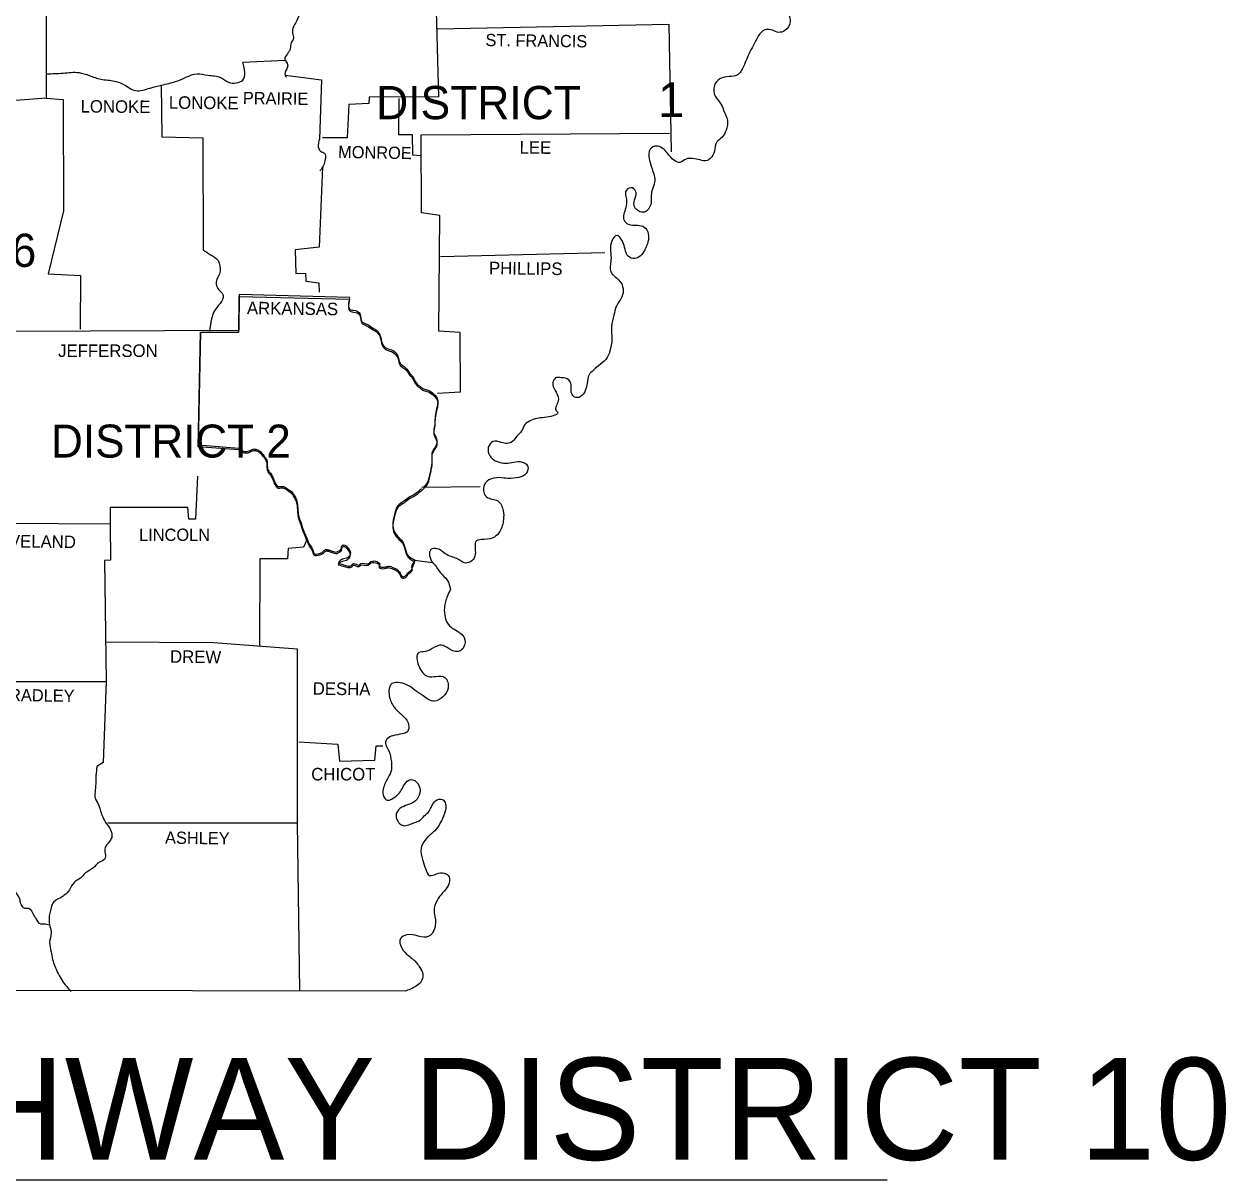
# Model space of a CAD drawing. Extents: x 171 to 3403, y 68 to 2102.
# Drawn here: x 2999.8 to 3403.5, y 1284.9 to 1673 of the extents above; entities that cross this region are included whole.
import ezdxf

# ---------------------------------------------------------------- set-up
doc = ezdxf.new("R2010")
doc.units = 0
for name, color, linetype in [('1', 7, 'Continuous'), ('2', 7, 'Continuous'), ('3', 7, 'Continuous')]:
    doc.layers.add(name, color=color, linetype=linetype)

msp = doc.modelspace()

# ---------------------------------------------------------------- linework, layer by layer
at = {"layer": '1'}
for p, q in [((3133.42, 1517.43), (3152.99, 1517.73)), ((2625.16, 1284.87), (3289.7, 1284.87))]:
    msp.add_line(p, q, dxfattribs=at)
for points in [[(3000.75, 1871.52), (3000.95, 1848.23), (2999.28, 1848.13), (2999.58, 1823.77), (2992.73, 1822.79), (2993.32, 1816.24), (2995.66, 1813.2), (2995.47, 1805.48), (2982.16, 1804.99), (2981.67, 1793.05), (2969.54, 1792.66), (2968.95, 1778.18), (2969.64, 1777), (2969.93, 1753.91), (2990.87, 1752.54), (2990.58, 1700.98), (3007.21, 1700.49), (3007.21, 1648.05), (2994.1, 1647.07), (2993.12, 1635.53), (2971.11, 1635.43)], [(3137.53, 1702.16), (3139, 1648.54), (3115.71, 1648.44), (3115.62, 1646.29), (3108.87, 1645.9), (3108.28, 1634.74), (3100.06, 1634.74)], [(3138.71, 1671.34), (3216.39, 1672.9)], [(3216.39, 1672.9), (3217.18, 1630.05)], [(3073.25, 1660.18), (3087.44, 1660.87)], [(3087.44, 1655.78), (3099.67, 1654.21), (3098.98, 1634.25)], [(3045.86, 1652.55), (3046.05, 1635.04), (3059.85, 1634.74), (3059.95, 1597.17)], [(3007.21, 1648.05), (3012.88, 1647.66), (3012.98, 1610.28), (3007.89, 1589.05), (3018.75, 1588.56), (3018.66, 1570.56)], [(3125.69, 1647.95), (3125.6, 1635.82), (3130.1, 1635.82), (3130.29, 1629.07), (3133.13, 1628.77)], [(3138.71, 1549.03), (3146.34, 1549.52), (3146.24, 1569.39), (3139.1, 1569.87), (3139.49, 1608.72), (3133.33, 1609.6), (3133.13, 1635.72), (3216.59, 1636.31)], [(3100.06, 1624.86), (3098.89, 1598.05), (3090.86, 1597.17), (3091.06, 1589.25), (3094.29, 1589.35), (3094.39, 1586.61), (3098.79, 1586.12), (3098.89, 1582.89)], [(3139.69, 1594.92), (3194.87, 1596.29)], [(3109.06, 1581.13), (3072.08, 1582.1), (3071.88, 1570.07), (2997.03, 1569.78)], [(3059.06, 1569.48), (3071.88, 1569.48), (3072.08, 1581.52), (3109.06, 1580.54)], [(3059.06, 1569.48), (3058.28, 1531.62), (3071.88, 1530.54)], [(3071.88, 1529.96), (3058.28, 1531.03), (3059.06, 1569.48)], [(3057.99, 1521.15), (3057.4, 1506.77), (3055.15, 1506.77), (3054.76, 1510.58), (3028.73, 1510.58), (3028.73, 1505.1)], [(2993.9, 1505.4), (3028.54, 1505.2)], [(3028.73, 1505.2), (3028.83, 1492.97), (3026.78, 1492.87), (3027.36, 1452.27)], [(3094.87, 1500.02), (3093.7, 1497.37), (3088.51, 1496.89), (3088.22, 1493.36), (3078.93, 1493.36), (3078.83, 1464.11)], [(3105.83, 1495.71), (3106.13, 1496.01), (3106.42, 1496.3), (3106.42, 1496.3)], [(3027.07, 1465.58), (3063.37, 1465.28), (3091.55, 1463.13)], [(3091.55, 1463.13), (3091.55, 1404.62), (3092.33, 1348.36)], [(2983.14, 1452.17), (3027.36, 1452.27)], [(3027.36, 1452.27), (3026.39, 1425.07), (3024.23, 1423.7)], [(3092.04, 1431.92), (3105.15, 1431.14), (3105.73, 1425.46), (3117.57, 1425.85), (3118.06, 1430.65), (3120.31, 1430.65)], [(2769.26, 1428.1), (2769.46, 1348.95), (3128.04, 1348.36)], [(3027.95, 1404.72), (3091.55, 1404.72)]]:
    msp.add_lwpolyline(points, dxfattribs=at)
for points in [[(3099.86, 1713.51), (3099.37, 1710.28), (3097.52, 1709.4), (3095.36, 1707.24), (3094.87, 1705.29), (3093.11, 1704.5), (3091.45, 1702.45), (3090.37, 1699.61), (3090.37, 1696.68), (3091.06, 1693.35), (3093.5, 1692.47), (3094.68, 1690.51), (3094.48, 1688.46), (3096.83, 1687.09), (3097.22, 1685.91), (3096.83, 1684.64), (3095.75, 1681.02), (3095.85, 1678.58), (3095.66, 1677.5), (3093.02, 1676.81), (3091.45, 1674.17), (3090.37, 1672.31), (3089.98, 1669.87), (3090.28, 1668.11), (3089.49, 1666.74), (3089.2, 1664.68), (3088.22, 1662.92), (3087.34, 1661.26), (3088.32, 1659.3), (3088.03, 1657.93), (3087.44, 1655.78), (3087.93, 1655.09)], [(3252.89, 1709.59), (3253.28, 1706.75), (3251.62, 1703.72), (3251.03, 1700.69), (3251.32, 1697.65), (3248.19, 1695.99), (3245.45, 1694.03), (3247.02, 1691.69), (3249.95, 1689.53), (3252.89, 1687.87), (3254.75, 1686.21), (3255.24, 1682.2), (3255.72, 1679.65), (3256.7, 1676.13), (3257.09, 1673.68), (3255.33, 1670.75), (3253.28, 1670.16), (3251.13, 1670.85), (3248.58, 1671.04), (3246.53, 1669.09), (3245.06, 1666.35), (3243.59, 1663.61), (3242.52, 1661.26), (3241.44, 1658.71), (3239.29, 1655.78), (3236.65, 1655.29), (3233.51, 1654.51), (3231.66, 1652.35), (3231.95, 1648.73), (3233.71, 1646.29), (3235.08, 1643.26), (3236.06, 1640.61), (3235.57, 1637.29), (3234.2, 1634.84), (3232.44, 1633.37), (3231.66, 1630.24), (3230.38, 1627.89), (3229.21, 1627.11), (3226.86, 1627.31), (3224.32, 1627.8), (3222.16, 1627.6), (3220.11, 1626.52), (3218.06, 1627.21), (3215.9, 1629.56), (3214.14, 1631.32), (3212.19, 1632), (3210.13, 1630.93), (3209.74, 1627.7), (3210.72, 1624.37), (3211.6, 1619.87), (3210.72, 1617.13), (3210.42, 1612.63)], [(3007.4, 1656.27), (3012.88, 1656.46), (3018.26, 1656.66), (3021.69, 1655.68), (3025.6, 1654.41), (3030.2, 1653.82), (3033.43, 1652.55), (3037.25, 1650.59), (3042.14, 1651.47), (3045.95, 1652.45), (3050.94, 1653.72), (3054.17, 1655.09), (3057.89, 1656.27), (3061.61, 1655.78), (3065.82, 1655), (3068.46, 1653.43), (3073.25, 1654.12), (3073.25, 1660.18)], [(3098.98, 1634.25), (3098.59, 1632.3), (3099.37, 1630.24), (3100.74, 1629.56), (3100.94, 1627.6), (3100.45, 1625.64), (3100.06, 1624.86), (3099.18, 1623.69)], [(3210.42, 1612.63), (3208.17, 1609.79), (3204.85, 1611.56), (3204.85, 1613.9), (3205.34, 1616.35), (3204.16, 1617.91), (3202.11, 1617.23), (3202.11, 1614.2), (3201.91, 1611.26), (3201.32, 1607.05), (3202.69, 1605.78), (3205.83, 1605.39), (3208.08, 1604.8), (3209.45, 1602.55), (3209.35, 1599.81), (3208.27, 1597.17), (3206.71, 1595.02), (3204.26, 1594.24), (3202.3, 1595.51), (3201.52, 1598.05), (3200.64, 1600.3), (3198.98, 1601.97), (3197.22, 1600.11), (3196.82, 1596.68), (3196.92, 1593.75), (3196.92, 1589.74), (3199.47, 1587.09), (3201.03, 1584.06), (3200.54, 1581.32), (3198.68, 1578.09), (3197.9, 1575.26), (3197.12, 1571.44), (3197.22, 1567.23), (3196.53, 1563.12), (3195.16, 1560.38), (3192.62, 1558.13), (3190.95, 1556.67), (3189.58, 1555.2), (3188.9, 1552.26), (3188.41, 1550.21), (3186.55, 1547.76), (3185.08, 1547.57), (3183.91, 1548.55), (3183.52, 1550.21), (3183.52, 1551.87), (3182.74, 1553.54), (3180.29, 1554.22), (3178.33, 1554.12), (3177.45, 1552.75), (3178.72, 1548.94), (3179.21, 1546.49), (3178.53, 1543.16), (3178.92, 1542.77), (3175.4, 1540.91), (3172.56, 1540.62), (3170.21, 1539.94), (3167.96, 1538.47), (3166.88, 1536.32), (3165.32, 1534.55), (3163.95, 1532.89), (3162.09, 1532.11), (3160.04, 1532.5), (3157.3, 1532.79), (3155.73, 1530.84), (3156.22, 1528), (3158.08, 1526.34), (3160.82, 1525.55), (3163.66, 1525.75), (3166.4, 1526.04), (3168.94, 1524.67), (3168.45, 1522.03), (3166, 1520.76), (3162.38, 1520.37), (3159.45, 1520.66), (3155.93, 1519.88), (3154.17, 1517.63), (3155.14, 1514.2), (3158.96, 1512.83), (3160.72, 1509.61), (3160.82, 1506.57), (3159.55, 1502.56), (3157.79, 1500.7), (3154.36, 1499.92), (3151.72, 1499.43), (3151.33, 1494.93), (3150.15, 1492.68), (3148.1, 1491.99), (3145.16, 1493.46), (3143.4, 1494.15), (3141.25, 1495.12), (3138.51, 1496.79), (3136.46, 1496.49), (3137.04, 1492.19), (3137.24, 1491.99), (3139.59, 1488.76), (3141.94, 1486.22), (3143.01, 1483.19)], [(3059.95, 1597.17), (3062.39, 1595.51), (3064.93, 1593.55), (3065.62, 1590.91), (3065.42, 1589.05), (3064.64, 1587.49), (3064.45, 1585.04), (3065.62, 1583.28), (3066.7, 1581.81), (3065.62, 1579.17), (3063.76, 1576.72), (3062.78, 1573.98), (3062.1, 1569.87)], [(3109.06, 1581.13), (3109.35, 1577.12), (3111.7, 1576.53), (3112.68, 1575.45), (3113.17, 1573.2), (3114.83, 1572.22), (3117.08, 1570.85), (3118.45, 1569.87), (3119.43, 1568.31), (3120.02, 1565.77), (3121.58, 1564.1), (3123.74, 1563.32), (3125.3, 1561.46), (3126.28, 1558.82), (3127.85, 1557.64), (3129.41, 1555.59), (3130.19, 1554.71), (3131.56, 1552.36), (3132.93, 1551.19), (3133.91, 1550.5), (3135.48, 1550.01), (3137.43, 1548.74), (3138.71, 1546.78), (3138.71, 1545.32), (3138.22, 1543.07), (3137.83, 1540.72), (3137.63, 1538.08), (3137.43, 1535.73), (3138.32, 1533.77), (3137.83, 1530.84), (3136.85, 1529.27), (3136.75, 1527.12), (3136.46, 1523.89), (3136.07, 1522.03), (3135.18, 1519), (3133.91, 1517.43)], [(3109.06, 1580.54), (3109.35, 1576.53), (3111.7, 1575.94), (3112.68, 1574.86), (3113.17, 1572.61), (3114.83, 1571.64), (3117.08, 1570.27), (3118.45, 1569.29), (3119.43, 1567.72), (3120.02, 1565.18), (3121.58, 1563.52), (3123.74, 1562.73), (3125.3, 1560.87), (3126.28, 1558.23), (3127.85, 1557.06), (3129.41, 1555), (3130.19, 1554.12), (3131.56, 1551.77), (3132.93, 1550.6), (3133.91, 1549.92), (3135.48, 1549.43), (3137.43, 1548.15), (3138.71, 1546.2), (3138.71, 1544.73), (3138.22, 1542.48), (3137.83, 1540.13), (3137.63, 1537.49), (3137.43, 1535.14), (3138.32, 1533.18), (3137.83, 1530.25), (3136.85, 1528.68), (3136.75, 1526.53), (3136.46, 1523.3), (3136.07, 1521.44), (3135.18, 1518.41), (3133.62, 1516.55)], [(3071.88, 1530.54), (3073.35, 1529.56), (3075.4, 1529.66), (3076.77, 1530.25), (3077.85, 1530.15), (3079.32, 1529.27), (3080.3, 1528.1), (3080.98, 1527.22), (3081.47, 1525.85), (3081.47, 1524.57), (3081.96, 1522.81), (3082.55, 1522.13), (3083.33, 1520.86), (3083.82, 1519.68), (3084.11, 1518.9), (3085.19, 1517.63), (3086.17, 1517.73), (3087.05, 1517.63), (3088.22, 1516.94), (3089.98, 1515.57), (3090.28, 1515.18), (3091.45, 1512.64), (3091.65, 1511.07), (3091.84, 1509.02), (3092.23, 1507.06), (3093.02, 1504.91), (3093.41, 1503.44), (3094.29, 1501.39), (3094.87, 1500.02), (3095.66, 1498.26), (3096.83, 1496.3), (3097.32, 1495.12), (3098.98, 1495.22), (3100.16, 1495.71), (3101.04, 1496.49), (3102.11, 1496.4), (3103.29, 1496.01), (3104.85, 1495.71), (3105.83, 1496.3), (3106.32, 1496.69), (3106.42, 1497.57), (3107.3, 1498.06), (3108.28, 1497.37), (3109.35, 1495.81), (3109.35, 1494.83), (3108.96, 1494.24), (3107.69, 1493.46), (3105.93, 1492.87), (3105.44, 1492.19), (3107.1, 1491.41), (3109.75, 1491.21), (3110.43, 1491.8), (3112.19, 1491.31), (3112.88, 1491.8), (3115.23, 1491.7), (3116.3, 1492.48), (3118.45, 1492.39), (3119.14, 1491.9), (3119.14, 1491.02), (3120.9, 1490.62), (3122.17, 1490.92), (3123.84, 1490.43), (3125.3, 1489.65), (3126.09, 1488.57), (3127.06, 1487.4), (3127.94, 1487.69), (3128.63, 1488.57), (3130.1, 1490.13), (3130.1, 1491.11), (3130.49, 1491.8), (3130.98, 1492.78)], [(3130.98, 1492.19), (3130.49, 1491.21), (3130.1, 1490.53), (3130.1, 1489.55), (3128.63, 1487.98), (3127.94, 1487.1), (3127.06, 1486.81), (3126.09, 1487.98), (3125.3, 1489.06), (3123.84, 1489.84), (3122.17, 1490.33), (3120.9, 1490.04), (3119.14, 1490.43), (3119.14, 1491.31), (3118.45, 1491.8), (3116.3, 1491.9), (3115.23, 1491.11), (3112.88, 1491.21), (3112.19, 1490.72), (3110.43, 1491.21), (3109.75, 1490.62), (3107.1, 1490.82), (3105.44, 1491.6), (3105.93, 1492.29), (3107.69, 1492.87), (3108.96, 1493.66), (3109.35, 1494.24), (3109.35, 1495.22), (3108.28, 1496.79), (3107.3, 1497.47), (3106.42, 1496.98), (3106.32, 1496.1), (3105.83, 1495.71), (3104.85, 1495.12), (3103.29, 1495.42), (3102.11, 1495.81), (3101.04, 1495.91), (3100.16, 1495.12), (3098.98, 1494.64), (3097.32, 1494.54), (3096.83, 1495.71), (3095.66, 1497.67), (3094.87, 1499.43), (3094.29, 1500.8), (3093.41, 1502.85), (3093.02, 1504.32), (3092.23, 1506.47), (3091.84, 1508.43), (3091.65, 1510.49), (3091.45, 1512.05), (3090.28, 1514.59), (3089.98, 1514.99), (3088.22, 1516.36), (3087.05, 1517.04), (3086.17, 1517.14), (3085.19, 1517.04), (3084.11, 1518.31), (3083.82, 1519.1), (3083.33, 1520.27), (3082.55, 1521.54), (3081.96, 1522.23), (3081.47, 1523.99), (3081.47, 1525.26), (3080.98, 1526.63), (3080.3, 1527.51), (3079.32, 1528.68), (3077.85, 1529.56), (3076.77, 1529.66), (3075.4, 1529.08), (3073.35, 1528.98), (3071.88, 1529.96)], [(3133.23, 1516.85), (3131.17, 1515.18), (3129.41, 1514.2), (3127.55, 1512.83), (3125.3, 1511.17), (3124.23, 1508.33), (3123.64, 1504.42), (3124.42, 1502.07), (3126.18, 1500.02), (3127.36, 1498.35), (3128.24, 1495.42), (3130.39, 1493.36), (3131.08, 1493.07)], [(3133.62, 1516.55), (3131.17, 1514.59), (3129.41, 1513.62), (3127.55, 1512.25), (3125.3, 1510.58), (3124.23, 1507.75), (3123.64, 1503.83), (3124.42, 1501.48), (3126.18, 1499.43), (3127.36, 1497.77), (3128.24, 1494.83), (3130.39, 1492.78), (3131.08, 1492.48)], [(3143.01, 1483.19), (3142.03, 1480.94), (3140.96, 1477.02), (3141.25, 1473.7), (3142.72, 1470.86), (3145.07, 1469.29), (3147.61, 1467.04), (3147.41, 1463.62), (3145.95, 1462.35), (3142.52, 1463.23), (3139.88, 1464.4), (3137.63, 1463.72), (3134.6, 1462.25), (3132.35, 1461.96), (3132.45, 1457.26), (3135.48, 1453.93), (3138.12, 1453.93), (3141.15, 1453.54), (3142.23, 1450.02), (3140.47, 1447.08), (3137.53, 1445.62), (3133.81, 1447.38), (3131.17, 1449.24), (3128.53, 1451), (3125.2, 1451.88), (3123.35, 1451.49), (3122.47, 1447.38), (3124.03, 1443.66), (3126.57, 1441.12), (3128.92, 1437.79), (3128.53, 1435.34), (3126.77, 1434.66), (3123.64, 1433.97), (3121.78, 1433), (3121.29, 1432.21), (3122.27, 1428.89), (3123.15, 1425.27), (3123.15, 1422.53), (3122.07, 1419.98), (3120.41, 1416.07), (3120.61, 1413.53), (3121.78, 1412.35), (3123.25, 1412.74), (3125.2, 1414.11), (3126.48, 1415.68), (3127.55, 1417.63), (3129.61, 1419.3), (3132.15, 1417.83), (3132.74, 1414.8), (3131.27, 1412.16), (3129.22, 1410.98), (3126.67, 1410), (3124.81, 1407.85), (3125.3, 1405.31), (3126.77, 1403.94), (3130.39, 1404.62), (3132.84, 1405.7), (3134.21, 1407.07), (3135.87, 1408.73), (3136.75, 1410.39), (3138.02, 1412.16), (3140.27, 1412.64), (3141.35, 1411.18), (3140.96, 1407.85), (3139.59, 1404.72), (3137.73, 1402.08), (3135.67, 1400.22), (3133.13, 1396.21), (3133.62, 1392.49), (3134.6, 1389.46), (3135.97, 1387.11), (3138.32, 1387.6), (3140.96, 1387.89), (3142.52, 1386.62), (3142.33, 1383.88), (3140.37, 1381.24), (3138.51, 1378.69), (3137.53, 1375.17), (3137.92, 1372.73), (3137.92, 1370.48), (3137.14, 1368.03), (3135.77, 1366.66), (3132.15, 1366.76), (3128.34, 1367.15), (3126.28, 1365.97), (3126.67, 1362.65), (3128.92, 1360.2), (3130.49, 1358.93), (3132.74, 1356.19), (3133.72, 1353.94), (3133.42, 1351.98), (3132.05, 1350.32), (3128.04, 1348.36)], [(3024.23, 1423.7), (3023.94, 1420.67), (3023.84, 1417.83), (3023.65, 1415.09), (3023.65, 1413.04), (3024.82, 1410.79), (3025.51, 1408.63), (3026.19, 1406.77), (3027.56, 1404.33), (3028.83, 1402.47), (3029.22, 1399.83), (3028.44, 1398.46), (3026.97, 1396.4), (3026.87, 1392.69), (3025.11, 1391.51), (3022.86, 1389.55), (3021.59, 1388.67), (3020.22, 1387.79), (3018.75, 1386.23), (3016.6, 1384.76), (3015.04, 1382.31), (3013.28, 1380.46), (3011.81, 1379.48), (3009.75, 1378.21), (3008.87, 1376.25), (3008.19, 1372.63), (3008.48, 1369.99), (3008.87, 1367.64), (3008.38, 1364.7), (3008.87, 1361.47), (3009.36, 1358.93), (3010.14, 1356.68), (3011.22, 1354.14), (3012.59, 1351.79), (3015.53, 1348.17)], [(2926.69, 1401.1), (2928.25, 1402.18), (2929.72, 1402.76), (2931.19, 1402.47), (2932.75, 1402.27), (2934.12, 1402.47), (2935.88, 1402.18), (2937.35, 1401.3), (2939.01, 1400.61), (2940.68, 1400.61), (2942.14, 1400.61), (2943.42, 1399.73), (2945.77, 1399.83), (2947.72, 1400.61), (2949.68, 1401.2), (2952.32, 1401.49), (2954.67, 1399.83), (2956.33, 1398.46), (2957.7, 1396.89), (2958.68, 1395.13), (2959.76, 1394.15), (2961.52, 1393.47), (2962.89, 1393.17), (2964.55, 1392.69), (2965.43, 1392.29), (2966.21, 1390.44), (2967.49, 1387.89), (2969.93, 1387.01), (2972.96, 1388.18), (2975.41, 1388.87), (2977.17, 1389.46), (2978.25, 1389.85), (2979.23, 1389.95), (2978.93, 1390.14), (2980.11, 1390.44), (2981.18, 1389.65), (2981.87, 1388.58), (2983.04, 1387.01), (2984.12, 1385.64), (2985.19, 1385.15), (2986.27, 1385.74), (2987.74, 1385.25), (2989.01, 1384.76), (2990.48, 1384.37), (2991.75, 1384.27), (2993.41, 1383.88), (2994.69, 1383.19), (2995.86, 1382.51), (2997.03, 1381.24), (2998.21, 1379.28), (2998.6, 1377.72), (2999.97, 1376.15), (3001.24, 1376.15), (3003.1, 1373.61), (3003.78, 1372.63), (3005.25, 1370.87), (3006.33, 1370.87), (3008.38, 1370.48)]]:
    msp.add_spline(points, degree=3, dxfattribs=at)
at = {"layer": '3'}
msp.add_line((3130.78, 1492.97), (3136.95, 1492.19), dxfattribs=at)

# ---------------------------------------------------------------- texts
at = {"layer": '1'}
msp.add_text('1', height=11.74, dxfattribs=at).set_placement((3212.77, 1641.69))
at = {"layer": '2'}
for s, height, rotation, p in [('ST. FRANCIS', 4.1081, 359.2216, (3154.75, 1665.56)), ('LONOKE', 4.207, 359.4974, (3018.75, 1643.26)), ('LONOKE', 4.207, 359.4974, (3048.4, 1644.53)), ('PRAIRIE', 4.109, 359.2116, (3073.25, 1646.09)), ('MONROE', 4.108, 359.0331, (3105.25, 1627.99)), ('LEE', 4.207, 359.4327, (3166.2, 1629.46)), ('PHILLIPS', 4.206, 359.3179, (3155.93, 1588.95)), ('ARKANSAS', 4.206, 359.2678, (3074.62, 1575.55)), ('CLEVELAND', 4.207, 359.3377, (2983.73, 1497.37)), ('DREW', 4.206, 359.2258, (3048.79, 1458.53)), ('BRADLEY', 4.108, 359.1449, (2991.07, 1445.72)), ('DESHA', 4.206, 359.3704, (3096.73, 1447.77)), ('ASHLEY', 4.109, 359.2361, (3047.13, 1397.77))]:
    msp.add_text(s, height=height, rotation=rotation, dxfattribs=at).set_placement(p)
for s, height, p in [('JEFFERSON', 4.207, (3011.22, 1561.17)), ('LINCOLN', 4.109, (3038.42, 1499.43)), ('CHICOT', 4.207, (3096.24, 1419)), ('ARKANSAS HIGHWAY DISTRICT 10', 34.244, (2636.86, 1291.62))]:
    msp.add_text(s, height=height, dxfattribs=at).set_placement(p)
at = {"layer": '3'}
for s, height, p in [('DISTRICT', 11.154, (3118.06, 1641.01)), ('DISTRICT 6', 11.154, (2922.67, 1591.4)), ('DISTRICT 2', 11.056, (3008.87, 1527.41))]:
    msp.add_text(s, height=height, dxfattribs=at).set_placement(p)

doc.saveas('drawing.dxf')
